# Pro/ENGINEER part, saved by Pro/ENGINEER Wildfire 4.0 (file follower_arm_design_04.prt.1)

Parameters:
  METRIC = "NO"

Other parameters: PITCH, DRILL_DIAMETER, THREAD_DIAMETER, THREADS_PER_INCH, THREAD_DEPTH, THREAD_LENGTH, DRILL_POINT_ANGLE, DRILL_DEPTH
